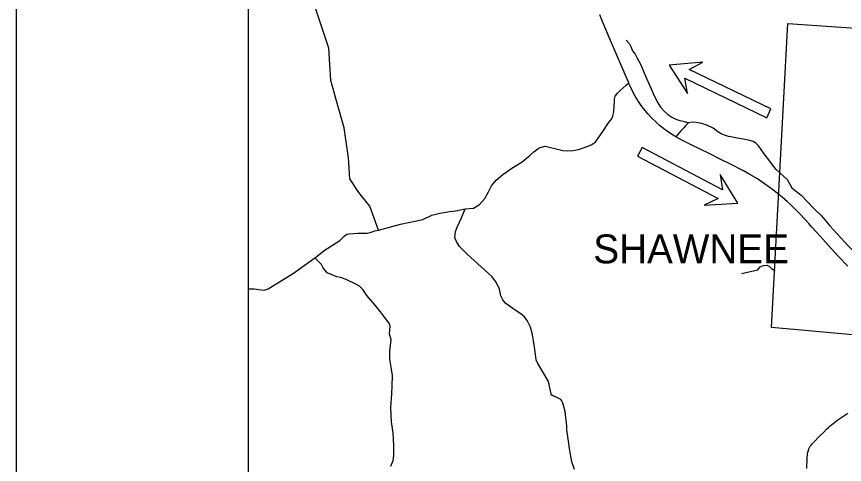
# Model space of a CAD drawing. Extents: x 2025369 to 2161369, y 549489 to 637489.
# Drawn here: x 2033369 to 2047673, y 581630 to 589374 of the extents above; entities that cross this region are included whole.
import ezdxf

# ---------------------------------------------------------------- set-up
doc = ezdxf.new("R2010")
doc.units = 0
for name, color, linetype in [('GM_X_City_Street', 7, 'Continuous'), ('GM_X_Corporation', 7, 'Continuous'), ('GM_X_Corporation_Text', 7, 'Continuous'), ('GM_X_County_Road', 7, 'Continuous'), ('GM_X_State_Route', 7, 'Continuous'), ('GM_X_Township_Road', 7, 'Continuous'), ('SH_Border', 7, 'Continuous'), ('SH_Text', 7, 'Continuous')]:
    doc.layers.add(name, color=color, linetype=linetype)

msp = doc.modelspace()

# ---------------------------------------------------------------- linework, layer by layer
at = {"layer": 'GM_X_City_Street'}
msp.add_lwpolyline([(2046557, 586673), (2046684, 586556), (2046762, 586413), (2046923, 586284), (2047031, 586177), (2047152, 586051), (2047277, 585930), (2047422, 585753), (2047736, 585410), (2047907, 585239), (2048106, 585040), (2048228, 584934), (2048253, 584918), (2048376, 584841), (2048677, 584684), (2048954, 584538), (2049195, 584391), (2049250, 584360), (2049259, 584354)], dxfattribs=at)
at = {"layer": 'GM_X_Corporation'}
msp.add_lwpolyline([(2046697, 589252), (2051467, 588925), (2051538, 588767), (2051612, 588915), (2055813, 588627), (2055503, 583275), (2051637, 583529), (2051605, 582941), (2051349, 582821), (2050728, 582314), (2050282, 582327), (2050354, 583521), (2049488, 583605), (2049465, 583759), (2049263, 583678), (2049195, 583526), (2048827, 583771), (2048760, 583886), (2048654, 583892), (2048645, 583798), (2046411, 583998)], close=True, dxfattribs=at)
at = {"layer": 'GM_X_County_Road'}
for points in [[(2039620, 585682), (2039474, 586095), (2039281, 586334), (2039128, 586571), (2039106, 586932), (2039031, 587450), (2038899, 587919), (2038797, 588270), (2038762, 588825), (2038480, 589681)], [(2043333, 587178), (2043364, 587196), (2043419, 587271), (2043485, 587369), (2043598, 587538), (2043646, 587601), (2043671, 587650), (2043684, 587696), (2043689, 587732), (2043697, 587912), (2043700, 587960), (2043706, 587977), (2043714, 587996), (2043733, 588026), (2043750, 588047), (2043799, 588095), (2043901, 588189), (2043945, 588227)], [(2046557, 586673), (2046492, 586731), (2046431, 586808), (2046384, 586876), (2046284, 587001), (2046221, 587095), (2046181, 587147), (2046142, 587185), (2046095, 587212), (2046040, 587230), (2045924, 587253), (2045821, 587271), (2045737, 587288), (2045670, 587301), (2045603, 587321), (2045542, 587347), (2045487, 587381), (2045405, 587443), (2045307, 587489), (2045210, 587523), (2045109, 587544), (2045041, 587547), (2044977, 587535), (2044927, 587485), (2044896, 587452), (2044879, 587434), (2044843, 587396), (2044759, 587297)], [(2042253, 586988), (2042305, 587037), (2042398, 587103), (2042502, 587135), (2042736, 587075), (2042808, 587058), (2042885, 587052), (2042981, 587058), (2043079, 587075), (2043246, 587133), (2043306, 587161), (2043333, 587178)], [(2039317, 585628), (2039359, 585628), (2039429, 585629), (2039497, 585648), (2039557, 585669), (2039620, 585682), (2040005, 585784), (2040390, 585867), (2040545, 585939), (2040682, 585973), (2040856, 586003), (2040961, 586018), (2041117, 586048), (2041265, 586063), (2041368, 586123), (2041457, 586230), (2041525, 586343), (2041576, 586446), (2041653, 586543), (2041772, 586645), (2041926, 586753), (2042103, 586861), (2042216, 586952), (2042231, 586966), (2042253, 586988)], [(2038563, 585234), (2038681, 585328), (2038955, 585503), (2039028, 585576), (2039076, 585613), (2039113, 585619), (2039189, 585624), (2039267, 585627), (2039305, 585628), (2039317, 585628)], [(2038663, 585039), (2038639, 585085), (2038523, 585201), (2038531, 585208), (2038563, 585234)], [(2039784, 584099), (2039741, 584155), (2039659, 584268), (2039566, 584382), (2039423, 584551), (2039351, 584656), (2039292, 584713), (2039217, 584755), (2039065, 584826), (2038964, 584864), (2038900, 584874), (2038733, 584943), (2038682, 585004), (2038663, 585039)], [(2039837, 581600), (2039877, 581697), (2039886, 581783), (2039887, 581955), (2039876, 582177), (2039848, 582369), (2039837, 582607), (2039852, 582853), (2039861, 582987), (2039863, 583167), (2039841, 583315), (2039816, 583453), (2039820, 583583), (2039840, 583793), (2039811, 583881), (2039826, 584024), (2039805, 584072), (2039784, 584099)]]:
    msp.add_lwpolyline(points, dxfattribs=at)
at = {"layer": 'GM_X_State_Route'}
for points in [[(2046510, 586320), (2046509, 586321), (2046437, 586379), (2046332, 586455), (2046250, 586512), (2046169, 586566), (2046038, 586645), (2045930, 586704), (2045704, 586822), (2045523, 586911), (2045345, 586998), (2045011, 587163), (2044872, 587233), (2044759, 587297), (2044683, 587342), (2044577, 587415), (2044474, 587499), (2044419, 587547), (2044336, 587628), (2044275, 587694), (2044180, 587811), (2044148, 587854), (2044112, 587908), (2044085, 587952), (2044057, 587999), (2044019, 588070), (2043971, 588168), (2043952, 588208), (2043945, 588227), (2043882, 588372), (2043758, 588667), (2043616, 589001), (2043505, 589262), (2043446, 589406)], [(2047731, 585057), (2047575, 585220), (2047446, 585366), (2047252, 585578), (2047112, 585733), (2047056, 585794), (2046987, 585871), (2046905, 585958), (2046804, 586062), (2046738, 586126), (2046691, 586169), (2046598, 586250), (2046510, 586320)], [(2047023, 581558), (2047031, 581736), (2047037, 581808), (2047042, 581841), (2047049, 581873), (2047057, 581898), (2047067, 581922), (2047080, 581944), (2047095, 581963), (2047113, 581986), (2047147, 582022), (2047242, 582119), (2047314, 582191), (2047363, 582241), (2047401, 582277), (2047426, 582299), (2047454, 582323), (2047499, 582357), (2047542, 582389), (2047731, 582516)]]:
    msp.add_lwpolyline(points, dxfattribs=at)
at = {"layer": 'GM_X_Township_Road'}
for points in [[(2043903, 588967), (2043960, 588905), (2043970, 588880), (2043980, 588855), (2044010, 588784), (2044056, 588723), (2044086, 588668), (2044152, 588539), (2044238, 588341), (2044334, 588125), (2044386, 588006), (2044447, 587880), (2044496, 587808), (2044561, 587734), (2044623, 587679), (2044690, 587635), (2044762, 587599), (2044826, 587575), (2044888, 587567), (2044977, 587535)], [(2042681, 582797), (2042675, 582800), (2042666, 582803), (2042643, 582812), (2042627, 582822), (2042619, 582831), (2042607, 582846), (2042603, 582852), (2042557, 583063), (2042445, 583260), (2042377, 583377), (2042346, 583437), (2042333, 583533), (2042325, 583620), (2042304, 583737), (2042277, 583898), (2042250, 584005), (2042192, 584117), (2042142, 584180), (2042083, 584233), (2041999, 584286), (2041900, 584357), (2041822, 584414), (2041771, 584475), (2041733, 584545), (2041714, 584662), (2041657, 584780), (2041579, 584877), (2041154, 585264), (2041022, 585400), (2040970, 585485), (2040941, 585551), (2040954, 585659), (2040981, 585731), (2041058, 585897), (2041117, 586048)], [(2037369, 584666), (2037409, 584668), (2037473, 584667), (2037555, 584653), (2037649, 584643), (2037717, 584667), (2038151, 584935), (2038419, 585126), (2038523, 585201)], [(2045894, 584932), (2046179, 584994), (2046218, 585048), (2046238, 585061), (2046282, 585071), (2046336, 585074), (2046376, 585050), (2046410, 585021), (2046439, 585001), (2046477, 584977)], [(2043009, 581545), (2042961, 581678), (2042921, 581906), (2042901, 582076), (2042877, 582226), (2042877, 582296), (2042859, 582444), (2042846, 582543), (2042820, 582651), (2042807, 582689), (2042796, 582714), (2042787, 582731), (2042777, 582746), (2042771, 582755), (2042765, 582760), (2042751, 582767), (2042725, 582778), (2042681, 582797)]]:
    msp.add_lwpolyline(points, dxfattribs=at)
at = {"layer": 'SH_Border'}
msp.add_lwpolyline([(2033369, 635489), (2159369, 635489), (2159369, 551489), (2033369, 551489)], close=True, dxfattribs=at)
at = {"layer": 'SH_Text'}
msp.add_lwpolyline([(2037369, 631489), (2037369, 571561), (2092420, 571561), (2092420, 631489)], dxfattribs=at)
for points in [[(2046330, 587626), (2046402, 587776), (2044987, 588458), (2045224, 588585), (2044643, 588532), (2044963, 588044), (2044915, 588308)], [(2044176, 587110), (2044098, 586963), (2045489, 586231), (2045248, 586113), (2045830, 586146), (2045527, 586644), (2045566, 586379)]]:
    msp.add_lwpolyline(points, close=True, dxfattribs=at)

# ---------------------------------------------------------------- texts
at = {"layer": 'GM_X_Corporation_Text'}
msp.add_text('SHAWNEE', height=500, rotation=0, dxfattribs=at).set_placement((2043333, 585107))

doc.saveas('drawing.dxf')
